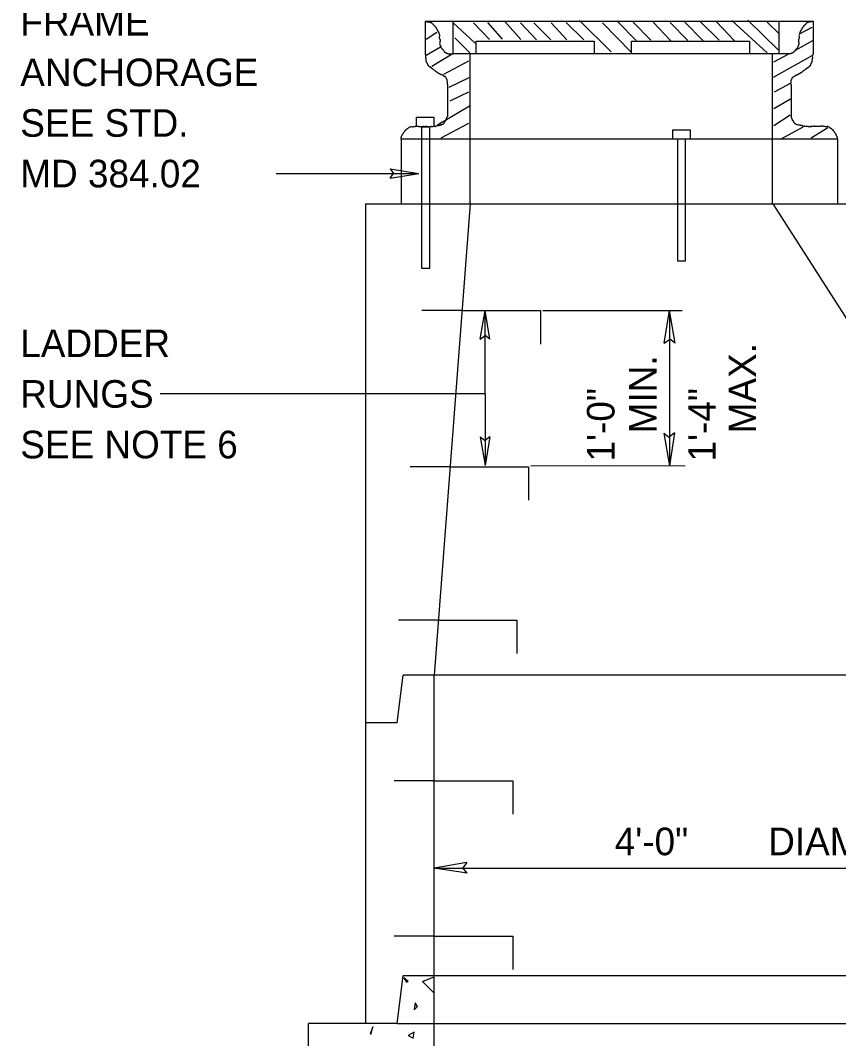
# Model space of a CAD drawing. Extents: x 8.6 to 15.9, y 6.4 to 16.6.
# Drawn here: x 8.761 to 10.539, y 12.809 to 15.023 of the extents above; entities that cross this region are included whole.
import ezdxf

# ---------------------------------------------------------------- set-up
doc = ezdxf.new("R2010")
doc.units = 0
for name, color, linetype in [('DETL-DIMS', 7, 'Continuous'), ('DETL-LINE', 7, 'Continuous'), ('DETL-NOTE', 7, 'Continuous'), ('DETL-PATT', 7, 'Continuous')]:
    doc.layers.add(name, color=color, linetype=linetype)

msp = doc.modelspace()

# ---------------------------------------------------------------- linework, layer by layer
at = {"layer": 'DETL-DIMS'}
for p, q in [((9.5643, 14.6999), (9.6266, 14.6895)), ((9.5643, 14.6999), (9.5721, 14.6895)), ((9.3166, 14.6895), (9.6266, 14.6895)), ((9.5643, 14.6792), (9.6266, 14.6895)), ((9.5643, 14.6792), (9.5721, 14.6895)), ((9.7605, 14.3299), (9.7709, 14.3921)), ((9.7709, 14.2106), (9.7709, 14.3921)), ((9.7813, 14.3299), (9.7709, 14.3921)), ((9.896, 14.3917), (10.1993, 14.392)), ((10.1602, 14.3207), (10.1715, 14.392)), ((10.1839, 14.321), (10.1715, 14.392)), ((10.1715, 14.392), (10.1715, 14.0546)), ((9.7605, 14.3299), (9.7709, 14.3377)), ((9.7813, 14.3299), (9.7709, 14.3377)), ((10.1602, 14.3207), (10.172, 14.3297)), ((10.1839, 14.321), (10.172, 14.3297)), ((9.7709, 14.2106), (9.0649, 14.2106)), ((9.7709, 14.2106), (9.7709, 14.0553)), ((10.1591, 14.1256), (10.1715, 14.0546)), ((10.1591, 14.1256), (10.171, 14.1168)), ((10.1828, 14.1258), (10.171, 14.1168)), ((10.1828, 14.1258), (10.1715, 14.0546)), ((9.7605, 14.1175), (9.7709, 14.0553)), ((9.7605, 14.1175), (9.7709, 14.1097)), ((9.7813, 14.1175), (9.7709, 14.0553)), ((9.7813, 14.1175), (9.7709, 14.1097)), ((9.8705, 14.0551), (10.206, 14.0546)), ((9.7315, 13.1924), (9.6604, 13.1802)), ((9.7315, 13.1924), (9.7226, 13.1805)), ((9.7316, 13.1687), (9.6604, 13.1802)), ((9.6604, 13.1802), (10.972, 13.1802)), ((9.7316, 13.1687), (9.7226, 13.1805))]:
    msp.add_line(p, q, dxfattribs=at)
at = {"layer": 'DETL-LINE'}
for p, q in [((9.641, 15.0206), (9.641, 14.9497)), ((9.641, 15.0206), (10.4839, 15.0206)), ((9.7017, 14.9495), (9.7017, 15.0206)), ((10.4092, 15.0213), (10.4092, 14.9495)), ((10.4839, 15.0206), (10.4839, 14.9497)), ((9.7518, 14.9495), (9.7518, 14.9775)), ((9.7518, 14.9775), (10.0081, 14.9775)), ((10.0081, 14.9775), (10.0081, 14.9495)), ((10.0893, 14.9493), (10.0893, 14.9773)), ((10.0893, 14.9773), (10.3456, 14.9773)), ((10.3456, 14.9773), (10.3456, 14.9493)), ((10.4232, 14.9495), (9.7017, 14.9495)), ((9.7381, 14.6237), (9.7381, 14.9495)), ((10.3957, 14.6237), (10.3957, 14.9495)), ((9.6891, 14.8832), (9.6891, 14.8133)), ((10.4358, 14.8832), (10.4358, 14.8133)), ((9.6217, 14.7917), (9.6217, 14.8118)), ((9.6217, 14.8118), (9.6598, 14.8118)), ((9.6598, 14.8118), (9.6598, 14.7932)), ((10.1786, 14.7646), (10.1786, 14.7847)), ((10.1786, 14.7847), (10.2167, 14.7847)), ((10.2167, 14.7847), (10.2167, 14.7646)), ((9.5882, 14.7646), (9.5882, 14.6237)), ((10.5367, 14.7646), (9.5882, 14.7646)), ((10.1888, 14.7646), (10.1888, 14.5)), ((10.2066, 14.5), (10.2066, 14.7646)), ((10.5367, 14.7646), (10.5367, 14.6237)), ((9.511, 14.6237), (9.511, 12.842)), ((9.511, 14.6237), (10.609, 14.6237)), ((9.7381, 14.6237), (9.6604, 13.5991)), ((10.972, 13.7241), (10.3968, 14.6237)), ((10.1888, 14.5), (10.2066, 14.5)), ((9.7205, 14.3917), (9.6336, 14.3917)), ((9.6948, 14.0524), (9.6079, 14.0524)), ((9.6695, 13.7187), (9.5826, 13.7187)), ((9.5795, 13.4955), (9.5929, 13.5991)), ((11.0541, 13.5991), (9.5929, 13.5991)), ((9.6604, 9.8494), (9.6604, 13.5991)), ((9.5795, 13.4955), (9.511, 13.4955)), ((9.6604, 13.3697), (9.5735, 13.3697)), ((9.6604, 13.0322), (9.5735, 13.0322)), ((9.5795, 12.842), (9.5929, 12.9456)), ((11.0541, 12.9456), (9.5929, 12.9456)), ((9.3872, 9.5164), (9.3872, 12.842)), ((9.5795, 12.842), (9.3872, 12.842)), ((9.5795, 12.842), (11.0675, 12.842))]:
    msp.add_line(p, q, dxfattribs=at)
msp.add_lwpolyline([(9.6329, 14.7904), (9.6329, 14.484), (9.6507, 14.484), (9.6507, 14.7904)], close=True, dxfattribs=at)
for points in [[(9.7205, 14.3917), (9.8912, 14.3917), (9.8912, 14.3191)], [(9.6948, 14.0524), (9.8655, 14.0524), (9.8655, 13.9798)], [(9.6695, 13.7187), (9.8402, 13.7187), (9.8402, 13.6461)], [(9.6604, 13.3697), (9.8311, 13.3697), (9.8311, 13.2971)], [(9.6604, 13.0322), (9.8311, 13.0322), (9.8311, 12.9596)]]:
    msp.add_lwpolyline(points, dxfattribs=at)
for points in [[(9.641, 15.0206), (9.6442, 15.0196), (9.6462, 15.0193), (9.6475, 15.0191), (9.6495, 15.0189), (9.6517, 15.0183), (9.6531, 15.018), (9.6542, 15.0175), (9.6548, 15.0165), (9.656, 15.0158), (9.6567, 15.0151), (9.6575, 15.014), (9.6584, 15.0129), (9.6588, 15.0125), (9.6598, 15.012), (9.6602, 15.0111), (9.6615, 15.0103), (9.6624, 15.0093), (9.6633, 15.008), (9.6641, 15.007), (9.6646, 15.0062), (9.6651, 15.0047), (9.666, 15.0037), (9.6665, 15.003), (9.667, 15.0018), (9.6676, 15.0004), (9.6685, 14.9986), (9.669, 14.9982), (9.6698, 14.9968), (9.6702, 14.9955), (9.6703, 14.9945), (9.6705, 14.9937), (9.6711, 14.9924), (9.6719, 14.9897), (9.6719, 14.9826), (9.6723, 14.9822), (9.6722, 14.9738), (9.6722, 14.9707), (9.6725, 14.9698), (9.673, 14.9686), (9.6735, 14.9675), (9.6744, 14.9662), (9.6748, 14.9635), (9.6762, 14.9618), (9.6765, 14.9612), (9.6775, 14.9608), (9.6788, 14.9595), (9.6794, 14.9585), (9.6801, 14.9577), (9.6809, 14.956), (9.6827, 14.9537), (9.684, 14.9531), (9.6853, 14.9524), (9.6862, 14.9515), (9.6879, 14.951), (9.6898, 14.9501), (9.6935, 14.9498), (9.6971, 14.9496), (9.7017, 14.9495)], [(10.4839, 15.0206), (10.4806, 15.0196), (10.4787, 15.0193), (10.4774, 15.0191), (10.4753, 15.0189), (10.4732, 15.0183), (10.4718, 15.018), (10.4706, 15.0175), (10.4701, 15.0165), (10.4688, 15.0158), (10.4682, 15.0151), (10.4674, 15.014), (10.4665, 15.0129), (10.466, 15.0125), (10.4651, 15.012), (10.4647, 15.0111), (10.4634, 15.0103), (10.4625, 15.0093), (10.4616, 15.008), (10.4608, 15.007), (10.4603, 15.0062), (10.4598, 15.0047), (10.4589, 15.0037), (10.4584, 15.003), (10.4579, 15.0018), (10.4573, 15.0004), (10.4564, 14.9986), (10.4559, 14.9982), (10.4551, 14.9968), (10.4546, 14.9955), (10.4546, 14.9945), (10.4544, 14.9937), (10.4538, 14.9924), (10.4529, 14.9897), (10.453, 14.9826), (10.4526, 14.9822), (10.4526, 14.9738), (10.4527, 14.9707), (10.4524, 14.9698), (10.4519, 14.9686), (10.4513, 14.9675), (10.4505, 14.9662), (10.4501, 14.9635), (10.4487, 14.9618), (10.4483, 14.9612), (10.4474, 14.9608), (10.4461, 14.9595), (10.4455, 14.9585), (10.4448, 14.9577), (10.4439, 14.956), (10.4422, 14.9537), (10.4409, 14.9531), (10.4396, 14.9524), (10.4386, 14.9515), (10.4369, 14.951), (10.4351, 14.9501), (10.4314, 14.9498), (10.4278, 14.9496), (10.4232, 14.9495)], [(9.6891, 14.8832), (9.6892, 14.8879), (9.6887, 14.8902), (9.6888, 14.8925), (9.6879, 14.8943), (9.6875, 14.8947), (9.687, 14.8961), (9.683, 14.9001), (9.6828, 14.9), (9.6826, 14.9001), (9.6818, 14.9014), (9.6804, 14.9023), (9.68, 14.9028), (9.6773, 14.9037), (9.6769, 14.9041), (9.6767, 14.904), (9.6765, 14.9041), (9.6748, 14.9048), (9.6733, 14.9055), (9.672, 14.906), (9.6707, 14.9073), (9.6694, 14.9073), (9.6689, 14.9082), (9.6676, 14.9091), (9.6659, 14.91), (9.6641, 14.9113), (9.6628, 14.9123), (9.6628, 14.9127), (9.6601, 14.914), (9.6584, 14.9158), (9.6566, 14.9172), (9.6549, 14.9181), (9.6549, 14.9185), (9.6535, 14.9194), (9.6531, 14.9198), (9.6513, 14.9203), (9.6513, 14.9212), (9.6491, 14.9221), (9.6491, 14.9225), (9.6483, 14.9239), (9.6478, 14.9243), (9.6465, 14.9252), (9.6461, 14.9265), (9.6456, 14.9288), (9.6444, 14.9303), (9.644, 14.9311), (9.6439, 14.9319), (9.6426, 14.9359), (9.6431, 14.9377), (9.6422, 14.9394), (9.6423, 14.9448), (9.6414, 14.9483), (9.641, 14.9497)], [(10.4358, 14.8832), (10.4357, 14.8879), (10.4362, 14.8902), (10.4361, 14.8925), (10.437, 14.8943), (10.4374, 14.8947), (10.4379, 14.8961), (10.4418, 14.9001), (10.442, 14.9), (10.4422, 14.9001), (10.4431, 14.9014), (10.4445, 14.9023), (10.4449, 14.9028), (10.4475, 14.9037), (10.448, 14.9041), (10.4482, 14.904), (10.4484, 14.9041), (10.45, 14.9048), (10.4515, 14.9055), (10.4528, 14.906), (10.4542, 14.9073), (10.4555, 14.9073), (10.4559, 14.9082), (10.4572, 14.9091), (10.459, 14.91), (10.4608, 14.9113), (10.4621, 14.9123), (10.4621, 14.9127), (10.4648, 14.914), (10.4665, 14.9158), (10.4682, 14.9172), (10.47, 14.9181), (10.47, 14.9185), (10.4713, 14.9194), (10.4718, 14.9198), (10.4735, 14.9203), (10.4735, 14.9212), (10.4758, 14.9221), (10.4758, 14.9225), (10.4766, 14.9239), (10.477, 14.9243), (10.4784, 14.9252), (10.4788, 14.9265), (10.4792, 14.9288), (10.4805, 14.9303), (10.4808, 14.9311), (10.481, 14.9319), (10.4823, 14.9359), (10.4818, 14.9377), (10.4827, 14.9394), (10.4826, 14.9448), (10.4835, 14.9483), (10.4839, 14.9497)], [(9.5882, 14.7646), (9.5882, 14.7653), (9.5883, 14.7662), (9.5885, 14.7676), (9.589, 14.7694), (9.5895, 14.7708), (9.5905, 14.7726), (9.5912, 14.7741), (9.5921, 14.7756), (9.5935, 14.7772), (9.5942, 14.7785), (9.5955, 14.7807), (9.5963, 14.7816), (9.5963, 14.7821), (9.5977, 14.783), (9.5977, 14.7834), (9.5986, 14.7847), (9.599, 14.7843), (9.6004, 14.786), (9.6017, 14.7869), (9.6017, 14.7873), (9.603, 14.7878), (9.6044, 14.7887), (9.6053, 14.79), (9.608, 14.7908), (9.6084, 14.7913), (9.6138, 14.7912), (9.6164, 14.7921), (9.619, 14.7921), (9.6195, 14.7925), (9.6204, 14.7925), (9.6217, 14.7925), (9.6244, 14.7925), (9.6262, 14.792), (9.6346, 14.7919), (9.6359, 14.7919), (9.6372, 14.7924), (9.639, 14.7919), (9.6448, 14.7918), (9.6456, 14.791), (9.647, 14.7918), (9.6483, 14.7914), (9.651, 14.7914), (9.6523, 14.7918), (9.6528, 14.7922), (9.6541, 14.7918), (9.6563, 14.7917), (9.6576, 14.7922), (9.659, 14.7922), (9.6603, 14.7926), (9.6616, 14.7921), (9.663, 14.7921), (9.6643, 14.793), (9.6683, 14.7943), (9.6696, 14.7943), (9.6696, 14.7947), (9.6714, 14.7947), (9.6745, 14.7956), (9.6754, 14.796), (9.6759, 14.7955), (9.6772, 14.7964), (9.6794, 14.7968), (9.6799, 14.7973), (9.6808, 14.7977), (9.6812, 14.7986), (9.6821, 14.7995), (9.6821, 14.8), (9.683, 14.8012), (9.6835, 14.8017), (9.6839, 14.8026), (9.6843, 14.8039), (9.6848, 14.8044), (9.6862, 14.8057), (9.6862, 14.807), (9.687, 14.8083), (9.6871, 14.8101), (9.688, 14.8118), (9.6889, 14.8132), (9.6891, 14.8133)], [(10.5367, 14.7646), (10.5367, 14.7653), (10.5366, 14.7662), (10.5364, 14.7676), (10.5359, 14.7694), (10.5353, 14.7708), (10.5344, 14.7726), (10.5337, 14.7741), (10.5328, 14.7756), (10.5314, 14.7772), (10.5307, 14.7785), (10.5294, 14.7807), (10.5285, 14.7816), (10.5285, 14.7821), (10.5272, 14.783), (10.5272, 14.7834), (10.5263, 14.7847), (10.5258, 14.7843), (10.5245, 14.786), (10.5232, 14.7869), (10.5232, 14.7873), (10.5218, 14.7878), (10.5205, 14.7887), (10.5196, 14.79), (10.5169, 14.7908), (10.5165, 14.7913), (10.5111, 14.7912), (10.5085, 14.7921), (10.5058, 14.7921), (10.5054, 14.7925), (10.5045, 14.7925), (10.5032, 14.7925), (10.5005, 14.7925), (10.4987, 14.792), (10.4903, 14.7919), (10.489, 14.7919), (10.4876, 14.7924), (10.4859, 14.7919), (10.4801, 14.7918), (10.4792, 14.791), (10.4779, 14.7918), (10.4766, 14.7914), (10.4739, 14.7914), (10.4726, 14.7918), (10.4721, 14.7922), (10.4708, 14.7918), (10.4686, 14.7917), (10.4672, 14.7922), (10.4659, 14.7922), (10.4646, 14.7926), (10.4632, 14.7921), (10.4619, 14.7921), (10.4606, 14.793), (10.4566, 14.7943), (10.4552, 14.7943), (10.4552, 14.7947), (10.4535, 14.7947), (10.4503, 14.7956), (10.4495, 14.796), (10.449, 14.7955), (10.4477, 14.7964), (10.4455, 14.7968), (10.445, 14.7973), (10.4441, 14.7977), (10.4437, 14.7986), (10.4428, 14.7995), (10.4428, 14.8), (10.4419, 14.8012), (10.4414, 14.8017), (10.441, 14.8026), (10.4405, 14.8039), (10.44, 14.8044), (10.4387, 14.8057), (10.4387, 14.807), (10.4378, 14.8083), (10.4378, 14.8101), (10.4369, 14.8118), (10.436, 14.8132), (10.4358, 14.8133)]]:
    msp.add_spline(points, degree=3, dxfattribs=at)
at = {"layer": 'DETL-PATT'}
for p, q in [((9.7018, 15.0168), (9.7493, 14.9731)), ((9.746, 15.0174), (9.7804, 14.9807)), ((9.8086, 14.9817), (9.7767, 15.0179)), ((9.8485, 14.9808), (9.8139, 15.0198)), ((9.8823, 14.9803), (9.8475, 15.0169)), ((9.9138, 14.9805), (9.8769, 15.017)), ((9.9482, 14.9802), (9.9146, 15.0175)), ((9.9856, 14.9805), (9.9469, 15.0177)), ((10.0448, 14.9544), (9.9762, 15.0224)), ((10.0882, 14.9536), (10.026, 15.0169)), ((10.0992, 14.9786), (10.0596, 15.019)), ((10.1308, 14.9795), (10.0923, 15.0187)), ((10.1744, 14.9783), (10.1362, 15.0186)), ((10.2111, 14.9791), (10.1732, 15.0181)), ((10.2449, 14.978), (10.2047, 15.0184)), ((10.2798, 14.9796), (10.239, 15.0195)), ((10.3127, 14.9779), (10.2737, 15.0193)), ((10.3835, 14.9521), (10.3073, 15.022)), ((10.408, 14.9588), (10.3419, 15.023)), ((10.409, 14.994), (10.3841, 15.0184)), ((10.4556, 14.9943), (10.4815, 15.008)), ((9.6429, 14.9819), (9.6657, 14.997)), ((9.7374, 14.9523), (9.705, 14.9842)), ((9.643, 14.9471), (9.6738, 14.965)), ((10.4824, 14.9777), (10.4444, 14.9569)), ((9.6994, 14.9488), (9.655, 14.9219)), ((10.4315, 14.9498), (10.3978, 14.9314)), ((10.3979, 14.8991), (10.4817, 14.9459)), ((9.6815, 14.9053), (9.7356, 14.9347)), ((9.7352, 14.8975), (9.692, 14.8766)), ((10.4337, 14.8854), (10.3989, 14.8662)), ((9.6953, 14.8474), (9.7358, 14.8669)), ((10.3982, 14.8312), (10.4342, 14.8521)), ((9.7373, 14.8363), (9.6677, 14.7947)), ((10.4341, 14.8163), (10.3982, 14.7931)), ((9.6755, 14.7673), (9.7355, 14.7993)), ((10.4155, 14.7657), (10.4623, 14.7908)), ((10.516, 14.7893), (10.4792, 14.7665))]:
    msp.add_line(p, q, dxfattribs=at)
for points in [[(9.6, 12.9321), (9.6036, 12.9338), (9.5942, 12.9414)], [(9.6187, 12.8872), (9.6165, 12.8721), (9.624, 12.8796)], [(9.5213, 12.8196), (9.5231, 12.8196), (9.5267, 12.8347)], [(9.6036, 12.8161), (9.6147, 12.8103), (9.6165, 12.8236)]]:
    msp.add_lwpolyline(points, close=True, dxfattribs=at)
msp.add_lwpolyline([(9.6604, 12.9085), (9.6351, 12.9338), (9.6578, 12.9432), (9.6604, 12.9425)], dxfattribs=at)

# ---------------------------------------------------------------- texts
at = {"layer": 'DETL-NOTE'}
for s, p in [('FRAME', (8.7608, 14.9895)), ('ANCHORAGE', (8.7608, 14.8795)), ('SEE STD.', (8.7608, 14.7695)), ('MD 384.02', (8.7608, 14.6595)), ('LADDER', (8.7608, 14.2906)), ('RUNGS', (8.7608, 14.1806)), ('SEE NOTE 6', (8.7608, 14.0706)), ('4\'-0"', (10.0525, 13.208)), ('DIAM.', (10.3861, 13.208))]:
    msp.add_text(s, height=0.06, dxfattribs=at).set_placement(p)
for s, p in [('MAX.', (10.3599, 14.125)), ('MIN.', (10.1437, 14.125)), ('1\'-0"', (10.0521, 14.0637)), ('1\'-4"', (10.2722, 14.0637))]:
    msp.add_text(s, height=0.06, rotation=90, dxfattribs=at).set_placement(p)

doc.saveas('drawing.dxf')
